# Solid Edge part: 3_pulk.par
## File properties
Author: Romil
Template: iso part.par
Last saved by: Romil
Revision: 31
Application: Solid Edge
Accuracy: 0.990
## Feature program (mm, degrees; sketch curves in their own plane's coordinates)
sketch for "unnamed Protrusion 1" plane through (0, 0, 0) normal (1, 0, 0) x-axis (0, 1, 0)
  arc centre (0, 0) radius 2.35 from (2.181, 0.875) to (2.181, -0.875) cw
  arc centre (0, 0) radius 2.35 from (-0.875, 2.181) to (0.875, 2.181) cw
  arc centre (0, 0) radius 2.35 from (-2.181, -0.875) to (-2.181, 0.875) cw
extrude "unnamed Protrusion 1" add finite 23.2 symmetric
fillet "Round_4" radius 0.55  Radii2 = 0.2 mm
mirror "unnamed Mirror 1" of "Round_4" about plane through (0, 0, 0) normal (1, 0, 0)
fillet "unnamed Round 1"
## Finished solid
Body 1: solid body, 50 faces, 128 edges, 80 vertices.
  Faces by surface: cylinder 24, torus 16, plane 10
  Edges by curve: circle 48, line 48, intersection 32
Bounding box of the edges (mm; curved faces can reach further): 23.200 x 4.700 x 4.700, from (-11.6, -2.35, -2.35) to (11.6, 2.35, 2.35).
Cylindrical faces by radius (mm): R0.1 x4, R0.2 x16, R2.35 x4
Toroidal faces (ring radius, tube radius in mm): R0.3 r0.2 x8, R1.8 r0.55 x8
Planar faces by outward normal: +x 1, +y 2, +z 2, -x 1, -y 2, -z 2
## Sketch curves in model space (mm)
arc centre (0, -0.975, -0.975) radius 0.1 from (0, -0.975, -0.875) through (0, -0.9023, -0.9064) to (0, -0.875, -0.975)
line (0, -0.875, -0.975) -> (0, -0.875, -2.181)
arc centre (0, 0, 0) radius 2.35 from (0, 0.875, -2.181) through (0, 0, -2.35) to (0, -0.875, -2.181)
line (0, 0.875, -2.181) -> (0, 0.875, -0.975)
arc centre (0, 0.975, -0.975) radius 0.1 from (0, 0.875, -0.975) through (0, 0.9064, -0.9023) to (0, 0.975, -0.875)
line (0, 0.975, -0.875) -> (0, 2.181, -0.875)
arc centre (0, 0, 0) radius 2.35 from (0, 2.181, 0.875) through (0, 2.35, 0) to (0, 2.181, -0.875)
line (0, 2.181, 0.875) -> (0, 0.975, 0.875)
arc centre (0, 0.975, 0.975) radius 0.1 from (0, 0.975, 0.875) through (0, 0.9023, 0.9064) to (0, 0.875, 0.975)
line (0, 0.875, 0.975) -> (0, 0.875, 2.181)
arc centre (0, 0, 0) radius 2.35 from (0, -0.875, 2.181) through (0, 0, 2.35) to (0, 0.875, 2.181)
line (0, -0.875, 2.181) -> (0, -0.875, 0.975)
arc centre (0, -0.975, 0.975) radius 0.1 from (0, -0.875, 0.975) through (0, -0.9064, 0.9023) to (0, -0.975, 0.875)
line (0, -0.975, 0.875) -> (0, -2.181, 0.875)
arc centre (0, 0, 0) radius 2.35 from (0, -2.181, -0.875) through (0, -2.35, 0) to (0, -2.181, 0.875)
line (0, -2.181, -0.875) -> (0, -0.975, -0.875)
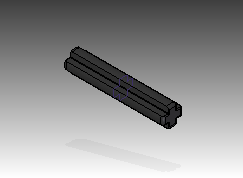
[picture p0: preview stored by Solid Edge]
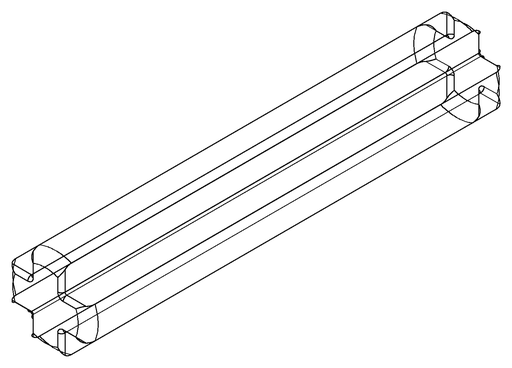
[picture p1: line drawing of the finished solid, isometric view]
